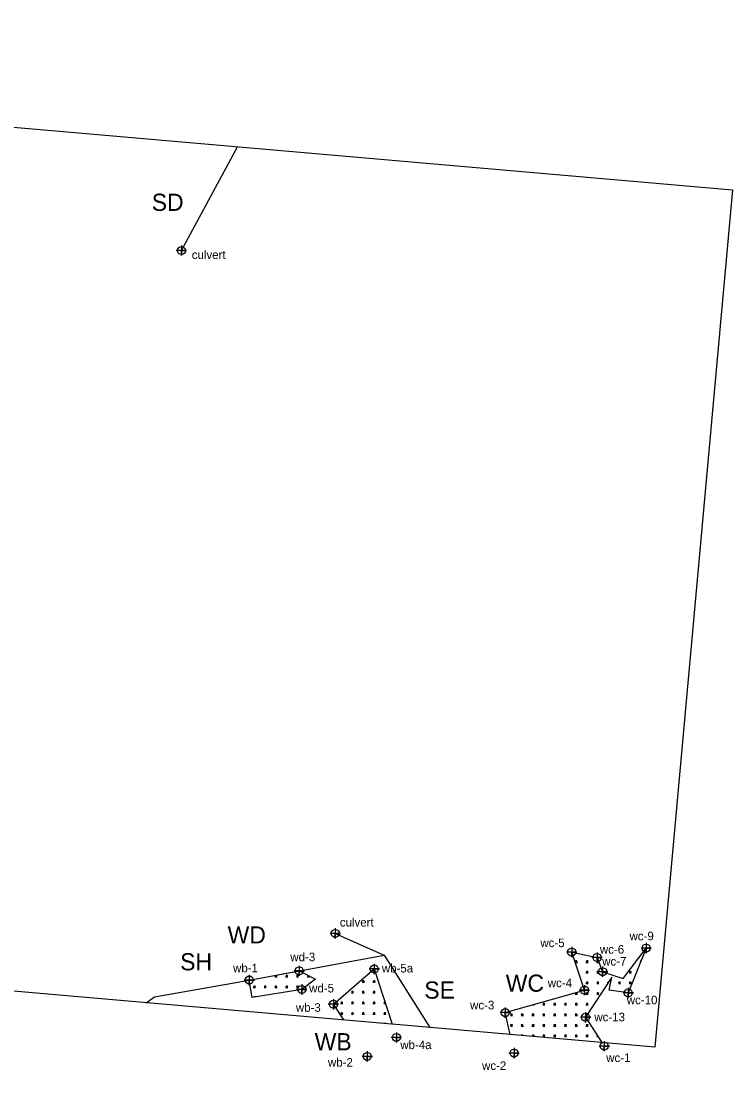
# Model space of a CAD drawing. Extents: x 1637473 to 1644249, y 841388 to 844031.
# Drawn here: x 1643835 to 1644249, y 841849 to 842471 of the extents above; entities that cross this region are included whole.
import ezdxf

# ---------------------------------------------------------------- set-up
doc = ezdxf.new("R2010")
doc.units = 0
for name, color, linetype in [('Default', 7, 'Continuous'), ('Exist Environmental Wetland Boundary', 7, 'Continuous'), ('Exist Environmental Wetland Boundary Cogo Number', 7, 'Continuous'), ('Exist Environmental Wetland Boundary Cogo Point CELL', 7, 'Continuous'), ('Exist Environmental Wetland Boundary Text', 7, 'Continuous'), ('Exist Hydro Jurisdictional Stream or Body of Water Mitigable', 7, 'Continuous'), ('Exist Hydro Jurisdictional Stream or Body of Water Mitigable Cogo Number', 7, 'Continuous'), ('Exist Hydro Jurisdictional Stream or Body of Water Mitigable Cogo Point CELL', 7, 'Continuous'), ('Exist Hydro Jurisdictional Stream or Body of Water Mitigable Text', 7, 'Continuous')]:
    doc.layers.add(name, color=color, linetype=linetype)

msp = doc.modelspace()

# ---------------------------------------------------------------- linework, layer by layer
at = {"layer": 'Default'}
msp.add_line((1644050.75, 841886.76), (1644050.41, 841886.79), dxfattribs=at)
for points in [[(1643123.93, 842470.88), (1644249.14, 842372.65), (1644203.72, 841873.41), (1644050.75, 841886.76)], [(1644050.41, 841886.79), (1643207.51, 841960.38), (1642457.5, 841546.57), (1642334.98, 841388.5), (1642010.83, 841639.74), (1641748.37, 841502.24), (1641281.09, 841734.92), (1641245.41, 841826.26), (1640567.36, 842176.47)]]:
    msp.add_lwpolyline(points, dxfattribs=at)
at = {"layer": 'Exist Environmental Wetland Boundary'}
for points in [[(1644119.48, 841880.76), (1644116.71, 841893.48), (1644162.8, 841906.58), (1644155.38, 841928.73), (1644170.15, 841925.61), (1644173.42, 841917.33), (1644185.39, 841913.29), (1644198.76, 841931.06), (1644188.29, 841904.96), (1644177.17, 841906.58), (1644178.79, 841914.22), (1644163.45, 841890.81), (1644172.99, 841876.09)], [(1644022.57, 841889.22), (1644016.62, 841898.41), (1644040.4, 841918.96), (1644050.78, 841886.76)]]:
    msp.add_lwpolyline(points, dxfattribs=at)
msp.add_lwpolyline([(1643998.17, 841907.02), (1643969.25, 841902.37), (1643967.6, 841912.49), (1643996.74, 841917.83), (1644006.11, 841913.03)], close=True, dxfattribs=at)
at = {"layer": 'Exist Environmental Wetland Boundary Cogo Point CELL'}
for points in [[(1644155.38, 841931.73), (1644155.38, 841925.73), (1644155.38, 841928.73), (1644158.38, 841928.73), (1644152.38, 841928.73)], [(1644198.76, 841934.06), (1644198.76, 841928.06), (1644198.76, 841931.06), (1644201.76, 841931.06), (1644195.76, 841931.06)], [(1644170.15, 841928.61), (1644170.15, 841922.61), (1644170.15, 841925.61), (1644173.15, 841925.61), (1644167.15, 841925.61)], [(1643996.72, 841920.84), (1643996.72, 841914.84), (1643996.72, 841917.84), (1643999.72, 841917.84), (1643993.72, 841917.84)], [(1644040.4, 841921.96), (1644040.4, 841915.96), (1644040.4, 841918.96), (1644043.4, 841918.96), (1644037.4, 841918.96)], [(1644173.42, 841920.33), (1644173.42, 841914.33), (1644173.42, 841917.33), (1644176.42, 841917.33), (1644170.42, 841917.33)], [(1643967.6, 841915.49), (1643967.6, 841909.49), (1643967.6, 841912.49), (1643970.6, 841912.49), (1643964.6, 841912.49)], [(1643998.17, 841910.02), (1643998.17, 841904.02), (1643998.17, 841907.02), (1644001.17, 841907.02), (1643995.17, 841907.02)], [(1644162.8, 841909.58), (1644162.8, 841903.58), (1644162.8, 841906.58), (1644165.8, 841906.58), (1644159.8, 841906.58)], [(1644188.29, 841907.96), (1644188.29, 841901.96), (1644188.29, 841904.96), (1644191.29, 841904.96), (1644185.29, 841904.96)], [(1644016.62, 841901.41), (1644016.62, 841895.41), (1644016.62, 841898.41), (1644019.62, 841898.41), (1644013.62, 841898.41)], [(1644116.71, 841896.48), (1644116.71, 841890.48), (1644116.71, 841893.48), (1644119.71, 841893.48), (1644113.71, 841893.48)], [(1644163.45, 841893.81), (1644163.45, 841887.81), (1644163.45, 841890.81), (1644166.45, 841890.81), (1644160.45, 841890.81)], [(1644053.27, 841882.02), (1644053.27, 841876.02), (1644053.27, 841879.02), (1644056.27, 841879.02), (1644050.27, 841879.02)], [(1644174.37, 841876.97), (1644174.37, 841870.97), (1644174.37, 841873.97), (1644177.37, 841873.97), (1644171.37, 841873.97)], [(1644036.33, 841870.99), (1644036.33, 841864.99), (1644036.33, 841867.99), (1644039.33, 841867.99), (1644033.33, 841867.99)], [(1644121.83, 841872.93), (1644121.83, 841866.93), (1644121.83, 841869.93), (1644124.83, 841869.93), (1644118.83, 841869.93)]]:
    msp.add_lwpolyline(points, dxfattribs=at)
for centre in [(1644198.76, 841931.06), (1644155.38, 841928.73), (1644170.15, 841925.61), (1643996.72, 841917.84), (1644040.4, 841918.96), (1644173.42, 841917.33), (1643967.6, 841912.49), (1643998.17, 841907.02), (1644162.8, 841906.58), (1644188.29, 841904.96), (1644016.62, 841898.41), (1644116.71, 841893.48), (1644163.45, 841890.81), (1644053.27, 841879.02), (1644174.37, 841873.97), (1644036.33, 841867.99), (1644121.83, 841869.93)]:
    msp.add_circle(centre, 2.34, dxfattribs=at)
at = {"layer": 'Exist Hydro Jurisdictional Stream or Body of Water Mitigable'}
for p, q in [((1643928.08, 842337.4), (1643960.8, 842397.82)), ((1644195.15, 841922.78), (1644195.44, 841922.78)), ((1644176.28, 841910.42), (1644176.3, 841910.42)), ((1644163.7, 841891.87), (1644164.14, 841891.87))]:
    msp.add_line(p, q, dxfattribs=at)
for points in [[(1644017.71, 841939.6), (1644046.25, 841926.95), (1644072.77, 841884.84)], [(1643907.58, 841899.26), (1643912.46, 841902.74), (1643967.6, 841912.49), (1644046.25, 841926.95)], [(1644157.41, 841922.78), (1644158.06, 841922.78), (1644158.06, 841923.97), (1644158.06, 841922.78), (1644158.7, 841922.78)], [(1644163.7, 841922.78), (1644164.35, 841922.78), (1644164.35, 841923.97), (1644164.35, 841922.78), (1644164.99, 841922.78)], [(1644169.99, 841922.78), (1644170.64, 841922.78), (1644170.64, 841923.97), (1644170.64, 841922.78), (1644171.27, 841922.78)], [(1644195.8, 841923.68), (1644195.8, 841923.97), (1644195.8, 841923.68)], [(1643982.47, 841914.31), (1643983.12, 841914.31), (1643983.12, 841915.34)], [(1643983.12, 841915.34), (1643983.12, 841914.31), (1643983.76, 841914.31)], [(1643988.76, 841914.31), (1643989.41, 841914.31), (1643989.41, 841915.49), (1643989.41, 841914.31), (1643990.05, 841914.31)], [(1643995.05, 841914.31), (1643995.7, 841914.31), (1643995.7, 841915.49), (1643995.7, 841914.31), (1643996.34, 841914.31)], [(1644001.34, 841914.31), (1644001.99, 841914.31), (1644001.99, 841915.14)], [(1644001.99, 841915.14), (1644001.99, 841914.31), (1644002.63, 841914.31)], [(1644039.62, 841917.33), (1644040.26, 841917.33), (1644040.26, 841918.52), (1644040.26, 841917.33), (1644040.91, 841917.33)], [(1644163.7, 841916.6), (1644164.35, 841916.6), (1644164.35, 841917.78), (1644164.35, 841916.6), (1644164.99, 841916.6)], [(1644169.99, 841916.6), (1644170.64, 841916.6), (1644170.64, 841917.78), (1644170.64, 841916.6), (1644171.28, 841916.6)], [(1644188.86, 841916.6), (1644189.51, 841916.6), (1644189.51, 841917.78), (1644189.51, 841916.6), (1644190.15, 841916.6)], [(1643969.89, 841908.12), (1643970.54, 841908.12), (1643970.54, 841909.31), (1643970.54, 841908.12), (1643971.18, 841908.12)], [(1643976.18, 841908.12), (1643976.83, 841908.12), (1643976.83, 841909.31), (1643976.83, 841908.12), (1643977.47, 841908.12)], [(1643982.47, 841908.12), (1643983.12, 841908.12), (1643983.12, 841909.31), (1643983.12, 841908.12), (1643983.76, 841908.12)], [(1643988.76, 841908.12), (1643989.41, 841908.12), (1643989.41, 841909.31), (1643989.41, 841908.12), (1643990.05, 841908.12)], [(1643995.05, 841908.12), (1643995.7, 841908.12), (1643995.7, 841909.31), (1643995.7, 841908.12), (1643996.34, 841908.12)], [(1644033.33, 841911.15), (1644033.97, 841911.15), (1644033.97, 841912.33), (1644033.97, 841911.15), (1644034.62, 841911.15)], [(1644039.62, 841911.15), (1644040.26, 841911.15), (1644040.26, 841912.33), (1644040.26, 841911.15), (1644040.91, 841911.15)], [(1644163.7, 841910.42), (1644164.35, 841910.42), (1644164.35, 841911.6), (1644164.35, 841910.42), (1644164.99, 841910.42)], [(1644169.99, 841910.42), (1644170.64, 841910.42), (1644170.64, 841911.6), (1644170.64, 841910.42), (1644171.28, 841910.42)], [(1644176.93, 841911.38), (1644176.93, 841911.6), (1644176.93, 841911.38)], [(1644182.57, 841910.42), (1644183.22, 841910.42), (1644183.22, 841911.6), (1644183.22, 841910.42), (1644183.86, 841910.42)], [(1644188.86, 841910.42), (1644189.51, 841910.42), (1644189.51, 841911.6), (1644189.51, 841910.42), (1644190.15, 841910.42)], [(1643970.54, 841902.57), (1643970.54, 841903.12), (1643970.54, 841902.57)], [(1644027.04, 841904.97), (1644027.68, 841904.97), (1644027.68, 841906.15), (1644027.68, 841904.97), (1644028.33, 841904.97)], [(1644033.33, 841904.97), (1644033.97, 841904.97), (1644033.97, 841906.15), (1644033.97, 841904.97), (1644034.62, 841904.97)], [(1644039.62, 841904.97), (1644040.26, 841904.97), (1644040.26, 841906.15), (1644040.26, 841904.97), (1644040.91, 841904.97)], [(1644157.41, 841904.23), (1644158.06, 841904.23), (1644158.06, 841905.24)], [(1644158.06, 841905.24), (1644158.06, 841904.23), (1644158.7, 841904.23)], [(1644163.7, 841904.23), (1644164.35, 841904.23), (1644164.35, 841905.42), (1644164.35, 841904.23), (1644164.99, 841904.23)], [(1644169.99, 841904.23), (1644170.64, 841904.23), (1644170.64, 841905.42), (1644170.64, 841904.23), (1644171.28, 841904.23)], [(1644020.75, 841898.78), (1644021.39, 841898.78), (1644021.39, 841899.97), (1644021.39, 841898.78), (1644022.04, 841898.78)], [(1644027.04, 841898.78), (1644027.68, 841898.78), (1644027.68, 841899.97), (1644027.68, 841898.78), (1644028.33, 841898.78)], [(1644033.33, 841898.78), (1644033.97, 841898.78), (1644033.97, 841899.97), (1644033.97, 841898.78), (1644034.62, 841898.78)], [(1644039.62, 841898.78), (1644040.26, 841898.78), (1644040.26, 841899.97), (1644040.26, 841898.78), (1644040.91, 841898.78)], [(1644045.91, 841898.78), (1644046.55, 841898.78), (1644046.55, 841899.87)], [(1644046.55, 841899.87), (1644046.55, 841898.78), (1644046.9, 841898.78)], [(1644132.78, 841898.05), (1644132.9, 841898.05), (1644132.9, 841898.08)], [(1644132.9, 841898.08), (1644132.9, 841898.05), (1644133.54, 841898.05)], [(1644138.54, 841898.05), (1644139.19, 841898.05), (1644139.19, 841899.23), (1644139.19, 841898.05), (1644139.83, 841898.05)], [(1644144.83, 841898.05), (1644145.48, 841898.05), (1644145.48, 841899.23), (1644145.48, 841898.05), (1644146.12, 841898.05)], [(1644151.12, 841898.05), (1644151.77, 841898.05), (1644151.77, 841899.23), (1644151.77, 841898.05), (1644152.41, 841898.05)], [(1644157.41, 841898.05), (1644158.06, 841898.05), (1644158.06, 841899.23), (1644158.06, 841898.05), (1644158.7, 841898.05)], [(1644163.7, 841898.05), (1644164.35, 841898.05), (1644164.35, 841899.23), (1644164.35, 841898.05), (1644164.99, 841898.05)], [(1644020.75, 841892.6), (1644021.39, 841892.6), (1644021.39, 841893.78), (1644021.39, 841892.6), (1644022.04, 841892.6)], [(1644027.04, 841892.6), (1644027.68, 841892.6), (1644027.68, 841893.78), (1644027.68, 841892.6), (1644028.33, 841892.6)], [(1644033.33, 841892.6), (1644033.97, 841892.6), (1644033.97, 841893.78), (1644033.97, 841892.6), (1644034.62, 841892.6)], [(1644039.62, 841892.6), (1644040.26, 841892.6), (1644040.26, 841893.78), (1644040.26, 841892.6), (1644040.91, 841892.6)], [(1644045.91, 841892.6), (1644046.55, 841892.6), (1644046.55, 841893.78), (1644046.55, 841892.6), (1644047.2, 841892.6)], [(1644119.67, 841891.87), (1644120.32, 841891.87), (1644120.32, 841893.05), (1644120.32, 841891.87), (1644120.96, 841891.87)], [(1644125.96, 841891.87), (1644126.61, 841891.87), (1644126.61, 841893.05), (1644126.61, 841891.87), (1644127.25, 841891.87)], [(1644132.25, 841891.87), (1644132.9, 841891.87), (1644132.9, 841893.05), (1644132.9, 841891.87), (1644133.54, 841891.87)], [(1644138.54, 841891.87), (1644139.19, 841891.87), (1644139.19, 841893.05), (1644139.19, 841891.87), (1644139.83, 841891.87)], [(1644144.83, 841891.87), (1644145.48, 841891.87), (1644145.48, 841893.05), (1644145.48, 841891.87), (1644146.12, 841891.87)], [(1644151.12, 841891.87), (1644151.77, 841891.87), (1644151.77, 841893.05), (1644151.77, 841891.87), (1644152.41, 841891.87)], [(1644157.41, 841891.87), (1644158.06, 841891.87), (1644158.06, 841893.05), (1644158.06, 841891.87), (1644158.7, 841891.87)], [(1644164.35, 841892.18), (1644164.35, 841893.05), (1644164.35, 841892.18)], [(1644046.55, 841887.13), (1644046.55, 841887.6), (1644046.55, 841887.13)], [(1644119.67, 841885.68), (1644120.32, 841885.68), (1644120.32, 841886.87), (1644120.32, 841885.68), (1644120.96, 841885.68)], [(1644125.96, 841885.68), (1644126.61, 841885.68), (1644126.61, 841886.87), (1644126.61, 841885.68), (1644127.25, 841885.68)], [(1644132.25, 841885.68), (1644132.9, 841885.68), (1644132.9, 841886.87), (1644132.9, 841885.68), (1644133.54, 841885.68)], [(1644138.54, 841885.68), (1644139.19, 841885.68), (1644139.19, 841886.87), (1644139.19, 841885.68), (1644139.83, 841885.68)], [(1644144.83, 841885.68), (1644145.48, 841885.68), (1644145.48, 841886.87), (1644145.48, 841885.68), (1644146.12, 841885.68)], [(1644151.12, 841885.68), (1644151.77, 841885.68), (1644151.77, 841886.87), (1644151.77, 841885.68), (1644152.41, 841885.68)], [(1644157.41, 841885.68), (1644158.06, 841885.68), (1644158.06, 841886.87), (1644158.06, 841885.68), (1644158.7, 841885.68)], [(1644163.7, 841885.68), (1644164.35, 841885.68), (1644164.35, 841886.87), (1644164.35, 841885.68), (1644164.99, 841885.68)], [(1644126.61, 841880.14), (1644126.61, 841880.68), (1644126.61, 841880.14)], [(1644132.9, 841879.59), (1644132.9, 841880.68), (1644132.9, 841879.59)], [(1644138.54, 841879.5), (1644139.19, 841879.5), (1644139.19, 841880.68), (1644139.19, 841879.5), (1644139.83, 841879.5)], [(1644144.83, 841879.5), (1644145.48, 841879.5), (1644145.48, 841880.68), (1644145.48, 841879.5), (1644146.12, 841879.5)], [(1644151.12, 841879.5), (1644151.77, 841879.5), (1644151.77, 841880.68), (1644151.77, 841879.5), (1644152.41, 841879.5)], [(1644157.41, 841879.5), (1644158.06, 841879.5), (1644158.06, 841880.68), (1644158.06, 841879.5), (1644158.7, 841879.5)], [(1644163.7, 841879.5), (1644164.35, 841879.5), (1644164.35, 841880.68), (1644164.35, 841879.5), (1644164.99, 841879.5)], [(1644169.99, 841879.5), (1644170.64, 841879.5), (1644170.64, 841879.72)], [(1644170.64, 841879.72), (1644170.64, 841879.5), (1644170.78, 841879.5)]]:
    msp.add_lwpolyline(points, dxfattribs=at)
for centre, radius, start, end in [((1644157.14, 841922.72), 0.922, 4.14034, 67.53497), ((1644159.42, 841922.33), 1.44, 122.12745, 161.62219), ((1644163.43, 841922.72), 0.922, 4.14034, 67.53497), ((1644165.72, 841922.33), 1.44, 122.12745, 161.62219), ((1644169.72, 841922.72), 0.922, 4.14034, 67.53497), ((1644172.01, 841922.33), 1.44, 132.76383, 161.62219), ((1644194.88, 841922.72), 0.922, 35.50832, 67.53497), ((1643982.2, 841914.24), 0.922, 4.14034, 67.53497), ((1643984.48, 841913.85), 1.44, 122.12745, 161.62219), ((1643988.49, 841914.24), 0.922, 4.14034, 67.53497), ((1643990.77, 841913.85), 1.44, 122.12745, 161.62219), ((1643994.78, 841914.24), 0.922, 4.14034, 67.53497), ((1643997.06, 841913.85), 1.44, 122.12745, 161.62219), ((1644001.07, 841914.24), 0.922, 4.14034, 67.53497), ((1644003.35, 841913.85), 1.44, 131.66411, 161.62219), ((1644039.34, 841917.27), 0.922, 4.14034, 67.53497), ((1644041.63, 841916.88), 1.44, 129.62498, 161.62219), ((1644163.43, 841916.53), 0.922, 4.14034, 67.53497), ((1644165.72, 841916.15), 1.44, 122.12745, 161.62219), ((1644169.72, 841916.53), 0.922, 4.14034, 67.53497), ((1644172.01, 841916.15), 1.44, 122.12745, 161.62219), ((1644188.59, 841916.53), 0.922, 4.14034, 67.53497), ((1644190.88, 841916.15), 1.44, 122.12745, 161.62219), ((1643969.62, 841908.06), 0.922, 4.14034, 67.53497), ((1643971.9, 841907.67), 1.44, 122.12745, 161.62219), ((1643975.91, 841908.06), 0.922, 4.14034, 67.53497), ((1643978.19, 841907.67), 1.44, 122.12745, 161.62219), ((1643982.2, 841908.06), 0.922, 4.14034, 67.53497), ((1643984.48, 841907.67), 1.44, 122.12745, 161.62219), ((1643988.49, 841908.06), 0.922, 4.14034, 67.53497), ((1643990.77, 841907.67), 1.44, 122.12745, 161.62219), ((1643994.78, 841908.06), 0.922, 4.14034, 67.53497), ((1643997.06, 841907.67), 1.44, 122.12745, 161.62219), ((1644033.05, 841911.08), 0.922, 4.14034, 67.53497), ((1644035.34, 841910.7), 1.44, 122.12745, 161.62219), ((1644039.34, 841911.08), 0.922, 4.14034, 67.53497), ((1644041.63, 841910.7), 1.44, 122.12745, 161.62219), ((1644163.43, 841910.35), 0.922, 4.14034, 67.53497), ((1644165.72, 841909.96), 1.44, 122.12745, 161.62219), ((1644169.72, 841910.35), 0.922, 4.14034, 67.53497), ((1644172.01, 841909.96), 1.44, 122.12745, 161.62219), ((1644176.01, 841910.35), 0.922, 43.89208, 67.53497), ((1644182.3, 841910.35), 0.922, 4.14034, 67.53497), ((1644184.59, 841909.96), 1.44, 122.12745, 161.62219), ((1644188.59, 841910.35), 0.922, 4.14034, 67.53497), ((1644190.88, 841909.96), 1.44, 122.12745, 161.62219), ((1643969.62, 841901.87), 0.922, 45.50367, 67.53497), ((1643971.9, 841901.48), 1.44, 122.12745, 125.35757), ((1644026.76, 841904.9), 0.922, 4.14034, 67.53497), ((1644029.05, 841904.51), 1.44, 122.12745, 161.62219), ((1644033.05, 841904.9), 0.922, 4.14034, 67.53497), ((1644035.34, 841904.51), 1.44, 122.12745, 161.62219), ((1644039.34, 841904.9), 0.922, 4.14034, 67.53497), ((1644041.63, 841904.51), 1.44, 122.12745, 161.62219), ((1644157.14, 841904.17), 0.922, 4.14034, 67.53497), ((1644159.42, 841903.78), 1.44, 122.12745, 161.62219), ((1644163.43, 841904.17), 0.922, 4.14034, 67.53497), ((1644165.72, 841903.78), 1.44, 122.12745, 161.62219), ((1644169.72, 841904.17), 0.922, 4.14034, 67.53497), ((1644172.01, 841903.78), 1.44, 122.12745, 161.62219), ((1644020.47, 841898.72), 0.922, 4.14034, 67.53497), ((1644022.76, 841898.33), 1.44, 122.12745, 161.62219), ((1644026.76, 841898.72), 0.922, 4.14034, 67.53497), ((1644029.05, 841898.33), 1.44, 122.12745, 161.62219), ((1644033.05, 841898.72), 0.922, 4.14034, 67.53497), ((1644035.34, 841898.33), 1.44, 122.12745, 161.62219), ((1644039.34, 841898.72), 0.922, 4.14034, 67.53497), ((1644041.63, 841898.33), 1.44, 122.12745, 161.62219), ((1644045.63, 841898.72), 0.922, 4.14034, 67.53497), ((1644047.92, 841898.33), 1.44, 143.02433, 161.62219), ((1644131.98, 841897.98), 0.922, 4.14034, 6.16848), ((1644134.26, 841897.6), 1.44, 160.06534, 161.62219), ((1644138.27, 841897.98), 0.922, 4.14034, 67.53497), ((1644140.55, 841897.6), 1.44, 122.12745, 161.62219), ((1644144.56, 841897.98), 0.922, 4.14034, 67.53497), ((1644146.84, 841897.6), 1.44, 122.12745, 161.62219), ((1644150.85, 841897.98), 0.922, 4.14034, 67.53497), ((1644153.13, 841897.6), 1.44, 122.12745, 161.62219), ((1644157.14, 841897.98), 0.922, 4.14034, 67.53497), ((1644159.42, 841897.6), 1.44, 122.12745, 161.62219), ((1644163.43, 841897.98), 0.922, 4.14034, 67.53497), ((1644165.72, 841897.6), 1.44, 122.12745, 161.62219), ((1644020.47, 841892.53), 0.922, 4.14034, 67.53497), ((1644022.76, 841892.14), 1.44, 122.12745, 161.62219), ((1644026.76, 841892.53), 0.922, 4.14034, 67.53497), ((1644029.05, 841892.14), 1.44, 122.12745, 161.62219), ((1644033.05, 841892.53), 0.922, 4.14034, 67.53497), ((1644035.34, 841892.14), 1.44, 122.12745, 161.62219), ((1644039.34, 841892.53), 0.922, 4.14034, 67.53497), ((1644041.63, 841892.14), 1.44, 122.12745, 161.62219), ((1644045.63, 841892.53), 0.922, 4.14034, 67.53497), ((1644047.92, 841892.14), 1.44, 122.12745, 161.62219), ((1644119.4, 841891.8), 0.922, 4.14034, 67.53497), ((1644121.68, 841891.41), 1.44, 122.12745, 161.62219), ((1644125.69, 841891.8), 0.922, 4.14034, 67.53497), ((1644127.97, 841891.41), 1.44, 122.12745, 161.62219), ((1644131.98, 841891.8), 0.922, 4.14034, 67.53497), ((1644134.26, 841891.41), 1.44, 122.12745, 161.62219), ((1644138.27, 841891.8), 0.922, 4.14034, 67.53497), ((1644140.55, 841891.41), 1.44, 122.12745, 161.62219), ((1644144.56, 841891.8), 0.922, 4.14034, 67.53497), ((1644146.84, 841891.41), 1.44, 122.12745, 161.62219), ((1644150.85, 841891.8), 0.922, 4.14034, 67.53497), ((1644153.13, 841891.41), 1.44, 122.12745, 161.62219), ((1644157.14, 841891.8), 0.922, 4.14034, 67.53497), ((1644159.42, 841891.41), 1.44, 122.12745, 161.62219), ((1644163.43, 841891.8), 0.922, 19.19909, 67.53497), ((1644045.63, 841886.35), 0.922, 63.03445, 67.53497), ((1644047.92, 841885.96), 1.44, 122.12745, 128.68018), ((1644119.4, 841885.62), 0.922, 4.14034, 67.53497), ((1644121.68, 841885.23), 1.44, 122.12745, 161.62219), ((1644125.69, 841885.62), 0.922, 4.14034, 67.53497), ((1644127.97, 841885.23), 1.44, 122.12745, 161.62219), ((1644131.98, 841885.62), 0.922, 4.14034, 67.53497), ((1644134.26, 841885.23), 1.44, 122.12745, 161.62219), ((1644138.27, 841885.62), 0.922, 4.14034, 67.53497), ((1644140.55, 841885.23), 1.44, 122.12745, 161.62219), ((1644144.56, 841885.62), 0.922, 4.14034, 67.53497), ((1644146.84, 841885.23), 1.44, 122.12745, 161.62219), ((1644150.85, 841885.62), 0.922, 4.14034, 67.53497), ((1644153.13, 841885.23), 1.44, 122.12745, 161.62219), ((1644157.14, 841885.62), 0.922, 4.14034, 67.53497), ((1644159.42, 841885.23), 1.44, 122.12745, 161.62219), ((1644163.43, 841885.62), 0.922, 4.14034, 67.53497), ((1644165.72, 841885.23), 1.44, 122.12745, 161.62219), ((1644125.69, 841879.43), 0.922, 52.994, 67.53497), ((1644127.97, 841879.05), 1.44, 122.12745, 132.7498), ((1644131.98, 841879.43), 0.922, 9.77005, 67.53497), ((1644134.26, 841879.05), 1.44, 122.12745, 157.97123), ((1644138.27, 841879.43), 0.922, 4.14034, 67.53497), ((1644140.55, 841879.05), 1.44, 122.12745, 161.62219), ((1644144.56, 841879.43), 0.922, 4.14034, 67.53497), ((1644146.84, 841879.05), 1.44, 122.12745, 161.62219), ((1644150.85, 841879.43), 0.922, 4.14034, 67.53497), ((1644153.13, 841879.05), 1.44, 122.12745, 161.62219), ((1644157.14, 841879.43), 0.922, 4.14034, 67.53497), ((1644159.42, 841879.05), 1.44, 122.12745, 161.62219), ((1644163.43, 841879.43), 0.922, 4.14034, 67.53497), ((1644165.72, 841879.05), 1.44, 122.12745, 161.62219), ((1644169.72, 841879.43), 0.922, 4.14034, 67.53497), ((1644172.01, 841879.05), 1.44, 155.65273, 161.62219)]:
    msp.add_arc(centre, radius, start, end, dxfattribs=at)
at = {"layer": 'Exist Hydro Jurisdictional Stream or Body of Water Mitigable Cogo Point CELL'}
for points in [[(1643928.08, 842340.4), (1643928.08, 842334.4), (1643928.08, 842337.4), (1643931.08, 842337.4), (1643925.08, 842337.4)], [(1644017.71, 841942.6), (1644017.71, 841936.6), (1644017.71, 841939.6), (1644020.71, 841939.6), (1644014.71, 841939.6)]]:
    msp.add_lwpolyline(points, dxfattribs=at)
for centre in [(1643928.08, 842337.4), (1644017.71, 841939.6)]:
    msp.add_circle(centre, 2.34, dxfattribs=at)

# ---------------------------------------------------------------- texts
at = {"layer": 'Exist Environmental Wetland Boundary Cogo Number'}
for s, p in [('wc-9', (1644189.08, 841935.62)), ('wc-5', (1644137.14, 841931.65)), ('wc-6', (1644171.81, 841927.86)), ('wd-3', (1643991.49, 841923.44)), ('wc-7', (1644173.15, 841920.9)), ('wb-1', (1643958.16, 841916.99)), ('wb-5a', (1644044.82, 841916.89)), ('wc-4', (1644141.45, 841908.3)), ('wd-5', (1644002.46, 841905.27)), ('wc-3', (1644096.21, 841895.38)), ('wc-10', (1644187.47, 841898.36)), ('wb-3', (1643994.72, 841893.98)), ('wc-13', (1644168.59, 841888.43)), ('wb-4a', (1644055.57, 841872.26)), ('wc-1', (1644175.49, 841864.73)), ('wb-2', (1644013.42, 841862.05)), ('wc-2', (1644103.17, 841860.11))]:
    msp.add_text(s, height=5, dxfattribs=at).set_placement(p)
at = {"layer": 'Exist Environmental Wetland Boundary Text'}
for s, p in [('WD', (1643954.99, 841933.77)), ('WC', (1644116.97, 841905.68)), ('WB', (1644005.68, 841871.54))]:
    msp.add_text(s, height=10, dxfattribs=at).set_placement(p)
at = {"layer": 'Exist Hydro Jurisdictional Stream or Body of Water Mitigable Cogo Number'}
for p in [(1643934.11, 842332.44), (1644020.36, 841943.64)]:
    msp.add_text('culvert', height=5, dxfattribs=at).set_placement(p)
at = {"layer": 'Exist Hydro Jurisdictional Stream or Body of Water Mitigable Text'}
for s, p in [('SD', (1643910.78, 842360.5)), ('SH', (1643927.33, 841918.12)), ('SE', (1644069.54, 841901.65))]:
    msp.add_text(s, height=10, dxfattribs=at).set_placement(p)

doc.saveas('drawing.dxf')
